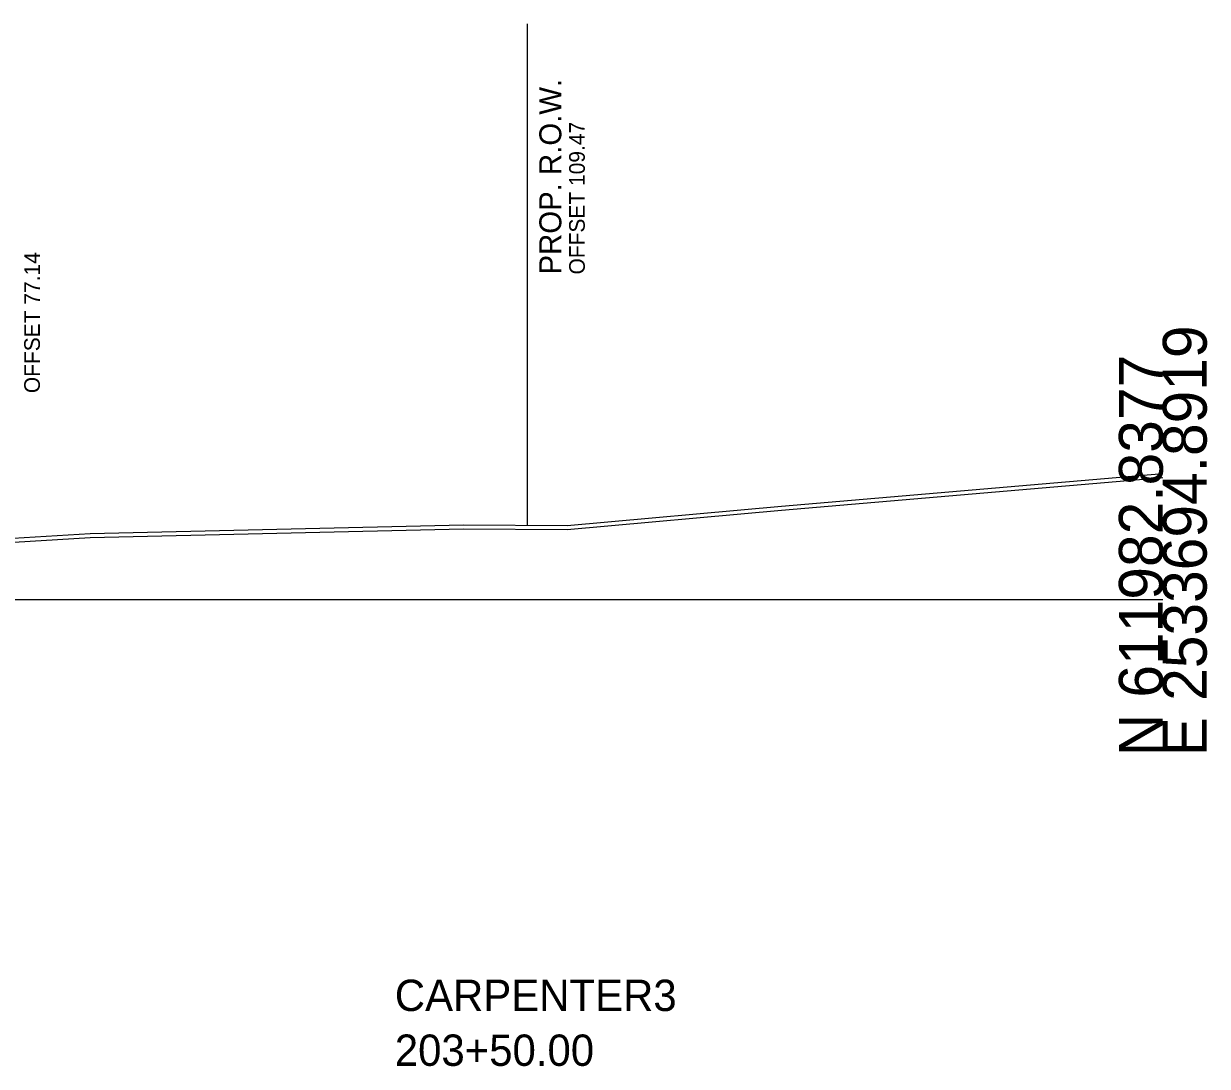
# Model space of a CAD drawing. Extents: x -120 to 2876, y -25 to 8560.
# Drawn here: x 227.3 to 302.8, y 6470.2 to 6536.7 of the extents above; entities that cross this region are included whole.
import ezdxf

# ---------------------------------------------------------------- set-up
doc = ezdxf.new("R2010")
doc.units = 0
for name, color, linetype in [('DESIGN - ROW - Right-of-Way and Easement Labels', 7, 'Continuous'), ('DESIGN - ROW - Right-of-Way Linework', 7, 'Continuous'), ('DESIGN - SHEET - Light Grid', 7, 'Continuous'), ('DESIGN - TYPICAL - Slope Tie Text', 7, 'Continuous'), ('DESIGN - TYPICAL - Warning Text', 7, 'Continuous'), ('SURVEY - GROUND - Bottom of Topsoil Layer', 7, 'Continuous'), ('SURVEY - GROUND - Top of Ground', 7, 'Continuous')]:
    doc.layers.add(name, color=color, linetype=linetype)

msp = doc.modelspace()

# ---------------------------------------------------------------- linework, layer by layer
at = {"layer": 'DESIGN - ROW - Right-of-Way Linework'}
msp.add_line((259.473, 6504.736), (259.473, 6536.736), dxfattribs=at)
at = {"layer": 'DESIGN - SHEET - Light Grid'}
msp.add_line((150, 6500), (300, 6500), dxfattribs=at)
at = {"layer": 'SURVEY - GROUND - Bottom of Topsoil Layer'}
for p, q in [((275.676, 6505.699), (300, 6507.788)), ((262.005, 6504.467), (275.676, 6505.699)), ((231.568, 6503.959), (255.392, 6504.518)), ((255.392, 6504.518), (262.005, 6504.467)), ((212.597, 6502.821), (231.568, 6503.959))]:
    msp.add_line(p, q, dxfattribs=at)
at = {"layer": 'SURVEY - GROUND - Top of Ground'}
msp.add_lwpolyline([(212.597, 6503.071), (231.568, 6504.209), (255.392, 6504.768), (262.005, 6504.717), (275.676, 6505.949), (300, 6508.038)], dxfattribs=at)

# ---------------------------------------------------------------- texts
at = {"layer": 'DESIGN - ROW - Right-of-Way and Easement Labels'}
for s, height, p in [('PROP. R.O.W.', 1.4, (261.623, 6520.736)), ('OFFSET 109.47', 1, (263.123, 6520.736))]:
    msp.add_text(s, height=height, rotation=90, dxfattribs=at).set_placement(p)
at = {"layer": 'DESIGN - SHEET - Light Grid'}
for s, p in [('E 2533694.8919', (302.8, 6490)), ('N 611982.8377', (300, 6490))]:
    msp.add_text(s, height=2.8, rotation=90, dxfattribs=at).set_placement(p)
at = {"layer": 'DESIGN - TYPICAL - Slope Tie Text'}
msp.add_text('OFFSET 77.14', height=1, rotation=90, dxfattribs=at).set_placement((228.356, 6513.166))
at = {"layer": 'DESIGN - TYPICAL - Warning Text'}
for s, p in [('CARPENTER3', (251, 6473.75)), ('203+50.00', (251, 6470.25))]:
    msp.add_text(s, height=2, dxfattribs=at).set_placement(p)

doc.saveas('drawing.dxf')
